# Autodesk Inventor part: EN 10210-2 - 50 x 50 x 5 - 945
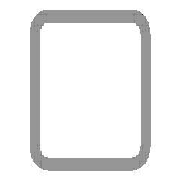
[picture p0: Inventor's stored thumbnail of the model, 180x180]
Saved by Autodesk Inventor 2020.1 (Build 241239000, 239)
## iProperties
_CCFamilyMember: 16
_CCFamilyDisplayName: DIN EN 10210-2 (USAS B17.1 quadratisch) - Rohrleitung — In Klammern angegebene Größen wurden aufgehoben
_FrameMemberDoc: Frame Member File
_Version: 15.0.0
_GetPNFromCC: 1
IsCustomPart: 1
Created: 2019-10
Part Number: EN 10210-2 - 50 x 50 x 5 - 945
Material: Stahl, weich
Description: Rohrleitung
Document SubType Name: Modeling
Standard: DIN
Designer: lutzd
Standard Revision: 2006-07
Standards Organization: DIN
Language: de-DE
Size Designation: 50 x 50 x 5
Categories: <MemberInstance><Categories><Category DisplayName="Profile" InternalName="089c4875-fa83-4c05-b084-43b9cc11f5ed" Mnemonic="GRDR"><CategoryParameter DisplayName="
Stock Number: 50 x 50 x 5
Mass: 6477.43 g
Surface Area: 3216.66 cm^2
Volume: 825.15 cm^3
Density: 7.85 g/cm^3
Appearance: Halbpoliert
G_L: 945,000 mm
G_W: 50,000 mm
G_H: 50,000 mm
Dimensions: 50x50x945 mm
Mass: 6,477 kg
DocNumber: ADSK-014099
Folder: .
+27D986D2-DFB7-4DAF-915B-D085B1D14DF5+SCHNITTDETAIL1: Schnittwinkel 90,00 grd
Title: Profil-Bauteil
Author: lutzd
Revision Number: -
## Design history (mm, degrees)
node "Startebene"
node "Endebene"
sketch "Skizze"
  geometry: L1 (-25, -17.5)-(-25, 17.5); L2 (-17.5, 25)-(17.5, 25); L3 (25, 17.5)-(25, -17.5); L4 (17.5, -25)-(-17.5, -25); L5 (-15, 20)-(15, 20); L6 (20, 15)-(20, -15); L7 (15, -20)-(-15, -20); L8 (-20, -15)-(-20, 15); L9 (0, 37.175)-(0, -37.175) reference; L10 (-37.175, 0)-(37.175, 0) reference; A1 r 7.5 centre (-17.5, -17.5) between (-25, -17.5) and (-17.5, -25); A2 r 7.5 centre (-17.5, 17.5) between (-17.5, 25) and (-25, 17.5); A3 r 7.5 centre (17.5, 17.5) between (25, 17.5) and (17.5, 25); A4 r 7.5 centre (17.5, -17.5) between (17.5, -25) and (25, -17.5); A5 r 5 centre (-15, -15) between (-20, -15) and (-15, -20); A6 r 5 centre (-15, 15) between (-15, 20) and (-20, 15); A7 r 5 centre (15, 15) between (20, 15) and (15, 20); A8 r 5 centre (15, -15) between (15, -20) and (20, -15)
  constraints: 16 end point, 16 point on circle, 16 tangent, 8 centre point, 6 equal radius, 4 parallel, 2 perpendicular, 2 other
  dimensions: "d7" = 7.5 radius of A1 (= G_IR); "d10" = 50 distance between parallel lines of L2 L4 (= G_H); "d11" = 50 distance between parallel lines of L1 L3 (= G_W); "d12" = 5 distance between parallel lines of L3 L6 (= G_T); "d15" = 25 distance between parallel lines of L2 L10 (= 0.5 x d10); "d16" = 25 distance between parallel lines of L9 L3 (= 0.5 x d11); "d19" = 5 radius of A5 (= G_T); "d20" = 5 distance between parallel lines of L4 L7 (= G_T)
extrude "Körper" new body sketch "Skizze" stored distance "d3" = 945 (= G_L); taper "d4" = 0 deg
node "Driven Length"
  sketch "Sketch3"
    geometry: L1 (0, 0)-(10, 0) reference
    constraints: 2 end point, 1 horizontal
  workplane "Work Plane3"
  sketch "Sketch4"
    geometry: L1 (-2, 70)-(12, 70) reference; L2 (-2, 1015)-(12, 1015) reference
    dimensions: "d18" = 945 distance between parallel lines of L1 L2 (derived)
workplane "Arbeitsebene4"
feature "Trennen1"
body "Solid1"
other parameters: "G_W" = 50 [user parameter; used in 1 equation term], "G_H" = 50 [user parameter; used in 1 equation term], "G_T" = 5 [user parameter; used in 3 equation terms], "G_IR" = 7.5 [user parameter; used in 1 equation term], "G_L" = 945 (= d18) [user parameter; used in 1 equation term], "G_OFFSET_END" = -35 [user parameter; used in 1 equation term], "d14" = 1015 (= G_OFFSET_END + B_L), "d17" = 90 deg
